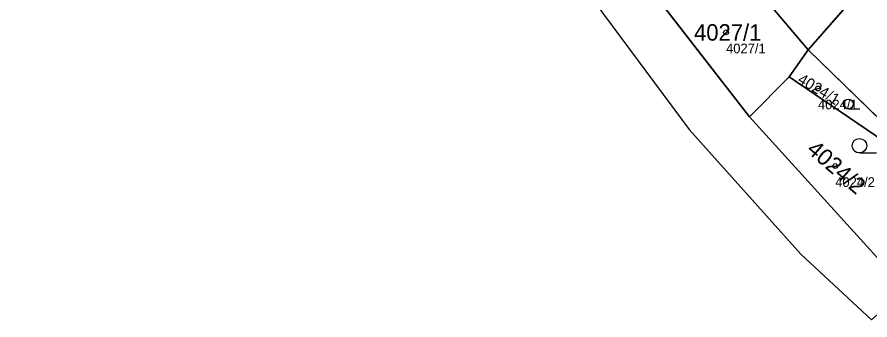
# Model space of a CAD drawing. Extents: x -754150 to -749824, y -1058608 to -1053956.
# Drawn here: x -753503.1 to -753415.1, y -1057985.2 to -1057954 of the extents above; entities that cross this region are included whole.
import ezdxf

# ---------------------------------------------------------------- set-up
doc = ezdxf.new("R2010")
doc.units = 0
for name, color, linetype in [('Vrstva 1', 7, 'Continuous'), ('Vrstva 2', 7, 'Continuous'), ('Vrstva 3', 7, 'Continuous'), ('Vrstva 50', 7, 'Continuous'), ('Vrstva 51', 7, 'Continuous'), ('Vrstva 53', 7, 'Continuous')]:
    doc.layers.add(name, color=color, linetype=linetype)

msp = doc.modelspace()

# ---------------------------------------------------------------- linework, layer by layer
at = {"layer": 'Vrstva 1'}
for p, q in [((-753411.24, -1057945.65), (-753421.47, -1057957.35)), ((-753438.69, -1057949.83), (-753427.52, -1057964.25)), ((-753421.47, -1057957.35), (-753425.3, -1057952.81)), ((-753421.47, -1057957.35), (-753423.43, -1057960.13)), ((-753421.47, -1057957.35), (-753407.4, -1057971.02)), ((-753423.43, -1057960.13), (-753427.52, -1057964.25)), ((-753423.43, -1057960.13), (-753407.4, -1057971.02)), ((-753427.52, -1057964.25), (-753414.05, -1057979.1)), ((-753422.2, -1057978.45), (-753414.93, -1057985.23))]:
    msp.add_line(p, q, dxfattribs=at)
msp.add_lwpolyline([(-753483.1, -1057907.88), (-753471.61, -1057918.29), (-753459.88, -1057931.27), (-753451.59, -1057941.76), (-753443.48, -1057952.45), (-753433.74, -1057965.58), (-753422.2, -1057978.45)], dxfattribs=at)
at = {"layer": 'Vrstva 3'}
for p, q in [((-753417.295, -1057963.44), (-753416.123, -1057963.44)), ((-753416.163, -1057967.99), (-753414.413, -1057967.99))]:
    msp.add_line(p, q, dxfattribs=at)
for centre, radius in [((-753417.295, -1057962.937), 0.502), ((-753416.163, -1057967.24), 0.75)]:
    msp.add_circle(centre, radius, dxfattribs=at)
at = {"layer": 'Vrstva 50'}
for centre in [(-753429.93, -1057955.54), (-753420.44, -1057961.33), (-753418.66, -1057969.34)]:
    msp.add_circle(centre, 0.25, dxfattribs=at)
at = {"layer": 'Vrstva 51'}
for points in [[(-753422.2, -1057978.45), (-753414.93, -1057985.23), (-753411.27, -1057981.94), (-753414.05, -1057979.1), (-753427.52, -1057964.25), (-753438.69, -1057949.83), (-753446.24, -1057939.49), (-753457.65, -1057926.47), (-753467.37, -1057915.88), (-753478.59, -1057904.54), (-753476.7, -1057902.49), (-753493.8, -1057891.83), (-753501.94, -1057892.53), (-753483.1, -1057907.88), (-753471.61, -1057918.29), (-753459.88, -1057931.27), (-753451.59, -1057941.76), (-753443.48, -1057952.45), (-753433.74, -1057965.58)], [(-753426.06, -1057939.46), (-753432.01, -1057944.41), (-753433.22, -1057945.39), (-753431.22, -1057948.2), (-753425.3, -1057943.54), (-753420.48, -1057948.96), (-753425.3, -1057952.81), (-753421.47, -1057957.35), (-753411.24, -1057945.65), (-753417.77, -1057936.33), (-753421.44, -1057935.62)], [(-753433.22, -1057945.39), (-753438.69, -1057949.83), (-753427.52, -1057964.25), (-753423.43, -1057960.13), (-753421.47, -1057957.35), (-753425.3, -1057952.81), (-753426.72, -1057951.25), (-753427.58, -1057952.19), (-753431.22, -1057948.2)], [(-753411.24, -1057945.65), (-753421.47, -1057957.35), (-753407.4, -1057971.02), (-753395.88, -1057956.9)], [(-753423.43, -1057960.13), (-753407.4, -1057971.02), (-753421.47, -1057957.35)], [(-753427.52, -1057964.25), (-753414.05, -1057979.1), (-753407.4, -1057971.02), (-753423.43, -1057960.13)]]:
    msp.add_lwpolyline(points, close=True, dxfattribs=at)
at = {"layer": 'Vrstva 53'}
for points in [[(-753667.61, -1057833.98), (-753654.98, -1057836.05), (-753626.4, -1057840.98), (-753621.79, -1057841.88), (-753591.26, -1057847.83), (-753576.4, -1057851.8), (-753575.2, -1057851.93), (-753551.94, -1057862.32), (-753537.49, -1057869.62), (-753521.78, -1057879.1), (-753503.84, -1057890.99), (-753501.94, -1057892.53), (-753483.1, -1057907.88), (-753471.61, -1057918.29), (-753459.88, -1057931.27), (-753451.59, -1057941.76), (-753443.48, -1057952.45), (-753433.74, -1057965.58)], [(-753433.74, -1057965.58), (-753422.2, -1057978.45), (-753414.93, -1057985.23)]]:
    msp.add_lwpolyline(points, dxfattribs=at)

# ---------------------------------------------------------------- texts
at = {"layer": 'Vrstva 2'}
msp.add_text('4027/1', height=1.7, dxfattribs=at).set_placement((-753433.235, -1057956.39))
for s, height, rotation, p in [('4024/1', 1.14, 329, (-753422.633, -1057960.676)), ('4024/2', 1.7, 319, (-753421.712, -1057967.812))]:
    msp.add_text(s, height=height, rotation=rotation, dxfattribs=at).set_placement(p)
at = {"layer": 'Vrstva 50'}
for s, p in [('4027/1', (-753429.93, -1057957.696)), ('4024/1', (-753420.44, -1057963.486)), ('4024/2', (-753418.66, -1057971.496))]:
    msp.add_text(s, height=1, dxfattribs=at).set_placement(p)

doc.saveas('drawing.dxf')
